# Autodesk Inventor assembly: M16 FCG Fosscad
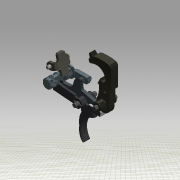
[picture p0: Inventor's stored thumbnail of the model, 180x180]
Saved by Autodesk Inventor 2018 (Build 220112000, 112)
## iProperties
Created: 2019-01
Part Number: M16 FCG Fosscad
Document SubType Name: Assembly
Designer: johne
Sending System: Autodesk Inventor 2018
Preprocessor: ST-DEVELOPER v16.13
Title: D:\Downloads\FA FCG.stp
Author: johne
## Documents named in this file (10)
- D:\Downloads\M16 FCG\M16 FCG Fosscad.iam
- D:\Downloads\M16 FCG\M16 Disco V2.ipt
- D:\Downloads\M16 FCG\Auto Sear Pin.ipt
- D:\Downloads\M16 FCG\Selector M16 V2.ipt
- D:\Downloads\M16 FCG\Auto Sear Bushing.ipt
- D:\Downloads\M16 FCG\Auto Sear.ipt
- D:\Downloads\M16 FCG\Auto Trigger.ipt
- D:\Downloads\M16 FCG\m-16-lower-auto-sear.ipt
- D:\Downloads\M16 FCG\M16 Hammer V6.ipt
- D:\Downloads\M16 FCG\Hammer Pin.ipt
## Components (10 placed, 10 different names)
1. M16 Disco:1 — Disco concentric fit, Disco fit to trigger, Disco front tang to trigger, Disco to Selector Tanget full auto, Hammer to Disco cocked SA trigger pulled
2. Selector M16 V2:1 — Autosear Tangent (Enable for Full auto position), Full auto position, Selector Concentric fit, Selector fit to lower, Trigger pulled in full auto, Disco to Selector Tanget full auto, Angle:6, Autosear Tangent for semi auto, Trigger to selector semi auto pulled
3. Sear:1 — Sear bushing concentric fit, Autosear Tangent (Enable for Full auto position), Autosear fit to lower, Autosear Tangent for semi auto, Hammer to autosear cocked
4. Trigger (1):1 — Disco concentric fit, Disco fit to trigger, Disco front tang to trigger, Trigger concentic to lower, Trigger fit to lower, Trigger pulled in full auto, Trigger pin concentric fit, Trigger to selector semi auto pulled, Trigger to hammer cocked semi auto
5. M16 Hammer V6:1 — Hammer concentric fit, Hammer to lower fit, Hammer pin concentric fit, Angle:5, Hammer to Disco cocked SA trigger pulled, Trigger to hammer cocked semi auto, Hammer to autosear cocked
6. Auto Sear Pin:1 — AS pin concentric fit, AS pin fit to lower
7. Sear Bushing:1 — AS pin concentric fit, Sear bushing concentric fit, AS concentric fit
8. m-16-lower-auto-sear:1 — Lower square to origin, Hammer concentric fit, Trigger concentic to lower, Selector Concentric fit, AS concentric fit, AS pin fit to lower, Autosear fit to lower, Hammer to lower fit, Trigger fit to lower, Selector fit to lower, Trigger pin flush to lower, Pin flush to lower, Angle:6, Full auto position
9. Hammer Pin:1 — Hammer pin concentric fit, Pin flush to lower
10. Trigger pin — Trigger pin concentric fit, Trigger pin flush to lower
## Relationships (30: Mate 16, Tangent 7, Angle 4, Flush 3)
- Disco concentric fit [Mate]: M16 Disco:1 ↔ Trigger (1):1
- Disco fit to trigger [Mate]: M16 Disco:1 ↔ Trigger (1):1
- AS pin concentric fit [Mate]: Auto Sear Pin:1 ↔ Sear Bushing:1
- Sear bushing concentric fit [Mate]: Sear:1 ↔ Sear Bushing:1
- Autosear Tangent (Enable for Full auto position) [Tangent]: Selector M16 V2:1 ↔ Sear:1
- Full auto position [Angle]: Selector M16 V2:1 ↔ m-16-lower-auto-sear:1
- Disco front tang to trigger [Mate]: M16 Disco:1 ↔ Trigger (1):1
- Lower square to origin [Angle]: m-16-lower-auto-sear:1
- Hammer concentric fit [Mate]: M16 Hammer V6:1 ↔ m-16-lower-auto-sear:1
- Trigger concentic to lower [Mate]: Trigger (1):1 ↔ m-16-lower-auto-sear:1
- Selector Concentric fit [Mate]: Selector M16 V2:1 ↔ m-16-lower-auto-sear:1
- AS concentric fit [Mate]: Sear Bushing:1 ↔ m-16-lower-auto-sear:1
- AS pin fit to lower [Flush]: Auto Sear Pin:1 ↔ m-16-lower-auto-sear:1
- Autosear fit to lower [Mate]: Sear:1 ↔ m-16-lower-auto-sear:1
- Hammer to lower fit [Mate]: M16 Hammer V6:1 ↔ m-16-lower-auto-sear:1
- Trigger fit to lower [Mate]: Trigger (1):1 ↔ m-16-lower-auto-sear:1
- Selector fit to lower [Mate]: Selector M16 V2:1 ↔ m-16-lower-auto-sear:1
- Trigger pulled in full auto [Tangent]: Selector M16 V2:1 ↔ Trigger (1):1
- Disco to Selector Tanget full auto [Tangent]: M16 Disco:1 ↔ Selector M16 V2:1
- Hammer pin concentric fit [Mate]: M16 Hammer V6:1 ↔ Hammer Pin:1
- Trigger pin concentric fit [Mate]: Trigger (1):1 ↔ Trigger pin
- Trigger pin flush to lower [Flush]: m-16-lower-auto-sear:1 ↔ Trigger pin
- Pin flush to lower [Flush]: m-16-lower-auto-sear:1 ↔ Hammer Pin:1
- Angle:5: M16 Hammer V6:1
- Angle:6: Selector M16 V2:1 ↔ m-16-lower-auto-sear:1
- Autosear Tangent for semi auto [Tangent]: Selector M16 V2:1 ↔ Sear:1
- Trigger to selector semi auto pulled [Tangent]: Selector M16 V2:1 ↔ Trigger (1):1
- Hammer to Disco cocked SA trigger pulled [Tangent]: M16 Disco:1 ↔ M16 Hammer V6:1
- Trigger to hammer cocked semi auto [Mate]: Trigger (1):1 ↔ M16 Hammer V6:1
- Hammer to autosear cocked [Tangent]: Sear:1 ↔ M16 Hammer V6:1
